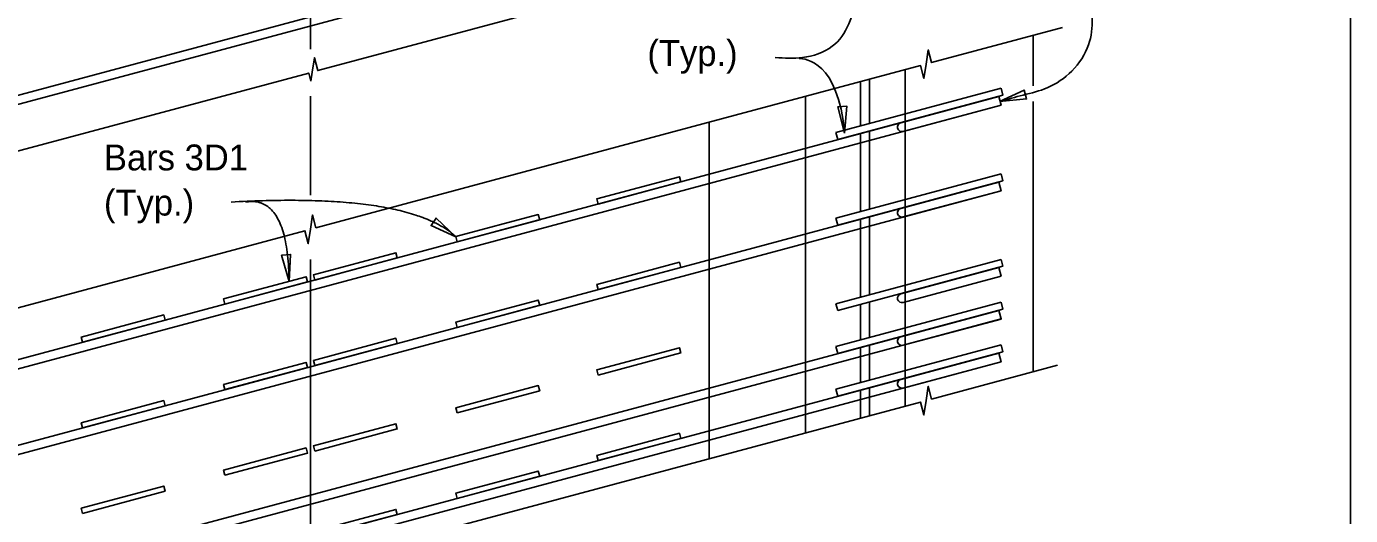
# Model space of a CAD drawing. Extents: x 120700.3 to 120754.4, y 120608.4 to 120631.3.
# Drawn here: x 120723.33 to 120731.07, y 120620 to 120622.85 of the extents above; entities that cross this region are included whole.
import ezdxf

# ---------------------------------------------------------------- set-up
doc = ezdxf.new("R2010")
doc.units = 0
for name, color, linetype in [('ActivePts-ConstElements', 7, 'Continuous'), ('BeamConc', 7, 'Continuous'), ('BeamConc_h', 7, 'Continuous'), ('CL_Major', 7, 'Continuous'), ('Dimension', 7, 'Continuous'), ('Rebar', 7, 'Continuous'), ('Rebar_h', 7, 'Continuous')]:
    doc.layers.add(name, color=color, linetype=linetype)

msp = doc.modelspace()

# ---------------------------------------------------------------- linework, layer by layer
at = {"layer": 'ActivePts-ConstElements'}
msp.add_lwpolyline([(120700.2847, 120610.4195), (120731.0726, 120610.4195), (120731.0726, 120629.8791), (120700.2847, 120629.8791)], close=True, dxfattribs=at)
at = {"layer": 'BeamConc'}
for p, q in [((120729.2163, 120622.802), (120729.2163, 120622.5065)), ((120727.8829, 120622.4448), (120727.8829, 120620.4782)), ((120729.2163, 120622.4153), (120729.2163, 120620.8354))]:
    msp.add_line(p, q, dxfattribs=at)
at = {"layer": 'BeamConc_h'}
for p, q in [((120728.4662, 120620.6344), (120728.4662, 120622.601)), ((120727.3204, 120622.2941), (120727.3204, 120620.3275))]:
    msp.add_line(p, q, dxfattribs=at)
at = {"layer": 'CL_Major'}
for p, q in [((120724.9871, 120622.7216), (120724.9871, 120627.6545)), ((120724.9871, 120621.8675), (120724.9871, 120622.4466)), ((120724.9871, 120619.9267), (120724.9871, 120621.4921))]:
    msp.add_line(p, q, dxfattribs=at)
at = {"layer": 'Dimension'}
for points in [[(120727.067, 120623.142), (120725.0301, 120622.5964), (120725.0101, 120622.6712), (120724.9976, 120622.5877), (120724.9897, 120622.5353)], [(120729.3877, 120622.8479), (120728.6218, 120622.6427), (120728.6018, 120622.7175), (120728.5893, 120622.634), (120728.5766, 120622.5503), (120728.5566, 120622.6252), (120727.0943, 120622.2335)], [(120724.9897, 120622.5353), (120724.9772, 120622.5821), (120722.272, 120621.8575)], [(120727.0943, 120622.2335), (120725.0196, 120621.6778), (120724.9996, 120621.7526), (120724.9871, 120621.6691), (120724.9744, 120621.5854), (120724.9544, 120621.6603), (120722.9331, 120621.1189)], [(120729.3589, 120620.8735), (120728.6218, 120620.6761), (120728.6018, 120620.7509), (120728.5893, 120620.6673), (120728.5766, 120620.5837), (120728.5566, 120620.6586), (120727.0943, 120620.2669)], [(120727.0943, 120620.2669), (120725.0196, 120619.7112), (120724.9996, 120619.786), (120724.9871, 120619.7024), (120724.9744, 120619.6188), (120724.9544, 120619.6937), (120722.9331, 120619.1523)]]:
    msp.add_lwpolyline(points, dxfattribs=at)
for points in [[(120729.0192, 120622.4159), (120729.1769, 120622.431), (120729.1631, 120622.4821)], [(120728.1126, 120622.2311), (120728.1251, 120622.389), (120728.0724, 120622.3843)], [(120725.8374, 120621.6255), (120725.7223, 120621.7343), (120725.6929, 120621.6903)], [(120724.8617, 120621.3641), (120724.8187, 120621.5165), (120724.8713, 120621.5222)]]:
    msp.add_lwpolyline(points, close=True, dxfattribs=at)
for points in [[(120728.1021, 120623.758), (120728.1838, 120623.0356), (120728.04, 120622.7381), (120727.8669, 120622.6727), (120727.7068, 120622.6727)], [(120729.7033, 120623.254), (120729.6282, 120623.254), (120729.54, 120623.1919), (120729.54, 120623.0645), (120729.54, 120622.7474), (120729.442, 120622.5938), (120729.2982, 120622.4957), (120729.1578, 120622.4533), (120729.0192, 120622.4159)]]:
    msp.add_spline(points, degree=3, dxfattribs=at)
for points, degree in [([(120727.8465, 120622.6672), (120727.8816, 120622.6656), (120728.0752, 120622.6508), (120728.1126, 120622.2311)], 3), ([(120724.5239, 120621.828), (120725.5579, 120621.8843), (120725.8374, 120621.6256)], 2), ([(120724.6078, 120621.828), (120724.856, 120621.8687), (120724.8618, 120621.3641)], 2)]:
    msp.add_open_spline(points, degree=degree, dxfattribs=at)
at = {"layer": 'Rebar'}
for p, q in [((120728.062, 120622.2338), (120729.028, 120622.4927)), ((120728.2058, 120622.5313), (120728.2058, 120622.2724)), ((120728.2579, 120622.5452), (120728.2579, 120622.2863)), ((120729.028, 120622.4927), (120729.0388, 120622.4524)), ((120729.0388, 120622.4524), (120728.0728, 120622.1936)), ((120728.4411, 120622.2909), (120729.0149, 120622.4446)), ((120729.0149, 120622.4446), (120729.0284, 120622.3943)), ((120729.0284, 120622.3943), (120728.4546, 120622.2406)), ((120728.0728, 120622.1936), (120728.062, 120622.2338)), ((120728.2058, 120622.2292), (120728.2058, 120621.7724)), ((120728.2579, 120622.2432), (120728.2579, 120621.7863)), ((120728.062, 120621.7338), (120729.028, 120621.9927)), ((120729.0388, 120621.9524), (120728.0728, 120621.6936)), ((120728.4411, 120621.7909), (120729.0149, 120621.9446)), ((120729.0149, 120621.9446), (120729.0284, 120621.8943)), ((120729.028, 120621.9927), (120729.0388, 120621.9524)), ((120729.0284, 120621.8943), (120728.4546, 120621.7406)), ((120728.0728, 120621.6936), (120728.062, 120621.7338)), ((120728.2058, 120621.7292), (120728.2058, 120621.2724)), ((120728.2579, 120621.7432), (120728.2579, 120621.2863)), ((120728.062, 120621.2338), (120729.028, 120621.4927)), ((120729.028, 120621.4927), (120729.0388, 120621.4524)), ((120729.0388, 120621.4524), (120728.0728, 120621.1936)), ((120728.4411, 120621.2909), (120729.0149, 120621.4446)), ((120729.0149, 120621.4446), (120729.0284, 120621.3943)), ((120729.0284, 120621.3943), (120728.4546, 120621.2406)), ((120728.062, 120620.9838), (120729.028, 120621.2427)), ((120728.0728, 120621.1936), (120728.062, 120621.2338)), ((120729.0388, 120621.2024), (120728.0728, 120620.9436)), ((120728.2058, 120621.2292), (120728.2058, 120621.0224)), ((120728.2579, 120621.2432), (120728.2579, 120621.0363)), ((120728.4411, 120621.0409), (120729.0149, 120621.1946)), ((120729.0149, 120621.1946), (120729.0284, 120621.1443)), ((120729.028, 120621.2427), (120729.0388, 120621.2024)), ((120729.0284, 120621.1443), (120728.4546, 120620.9906)), ((120728.062, 120620.7338), (120729.028, 120620.9927)), ((120728.0728, 120620.9436), (120728.062, 120620.9838)), ((120729.0388, 120620.9524), (120728.0728, 120620.6936)), ((120728.2058, 120620.9792), (120728.2058, 120620.7724)), ((120728.2579, 120620.9932), (120728.2579, 120620.7863)), ((120728.4411, 120620.7909), (120729.0149, 120620.9446)), ((120729.0149, 120620.9446), (120729.0284, 120620.8943)), ((120729.028, 120620.9927), (120729.0388, 120620.9524)), ((120729.0284, 120620.8943), (120728.4546, 120620.7406)), ((120728.0728, 120620.6936), (120728.062, 120620.7338)), ((120728.2058, 120620.7292), (120728.2058, 120620.5646)), ((120728.2579, 120620.7432), (120728.2579, 120620.5786))]:
    msp.add_line(p, q, dxfattribs=at)
for points in [[(120726.6708, 120621.8165), (120727.1537, 120621.9459), (120727.1457, 120621.9761), (120726.6627, 120621.8467)], [(120725.8455, 120621.5954), (120726.3285, 120621.7248), (120726.3204, 120621.755), (120725.8374, 120621.6256)], [(120725.0122, 120621.3721), (120725.4952, 120621.5015), (120725.4871, 120621.5317), (120725.0041, 120621.4023)], [(120726.6708, 120621.3165), (120727.1537, 120621.4459), (120727.1457, 120621.4761), (120726.6627, 120621.3467)], [(120724.4871, 120621.2314), (120724.97, 120621.3608), (120724.9619, 120621.391), (120724.479, 120621.2616)], [(120725.8455, 120621.0954), (120726.3285, 120621.2248), (120726.3204, 120621.255), (120725.8374, 120621.1256)], [(120723.6537, 120621.0081), (120724.1367, 120621.1375), (120724.1286, 120621.1677), (120723.6457, 120621.0383)], [(120725.0122, 120620.8721), (120725.4952, 120621.0015), (120725.4871, 120621.0317), (120725.0041, 120620.9023)], [(120726.6708, 120620.8165), (120727.1537, 120620.9459), (120727.1457, 120620.9761), (120726.6627, 120620.8467)], [(120724.4871, 120620.7314), (120724.97, 120620.8608), (120724.9619, 120620.891), (120724.479, 120620.7616)], [(120725.8455, 120620.5954), (120726.3285, 120620.7248), (120726.3204, 120620.755), (120725.8374, 120620.6256)], [(120723.6537, 120620.5081), (120724.1367, 120620.6375), (120724.1286, 120620.6677), (120723.6457, 120620.5383)], [(120725.0122, 120620.3721), (120725.4952, 120620.5015), (120725.4871, 120620.5317), (120725.0041, 120620.4023)], [(120726.6708, 120620.3165), (120727.1537, 120620.4459), (120727.1457, 120620.4761), (120726.6627, 120620.3467)], [(120724.4871, 120620.2314), (120724.97, 120620.3608), (120724.9619, 120620.391), (120724.479, 120620.2616)], [(120725.8455, 120620.0954), (120726.3285, 120620.2248), (120726.3204, 120620.255), (120725.8374, 120620.1256)], [(120723.6537, 120620.0081), (120724.1367, 120620.1375), (120724.1286, 120620.1677), (120723.6457, 120620.0383)], [(120725.0122, 120619.8721), (120725.4952, 120620.0015), (120725.4871, 120620.0317), (120725.0041, 120619.9023)]]:
    msp.add_lwpolyline(points, close=True, dxfattribs=at)
for centre in [(120728.4479, 120622.2657), (120728.4479, 120621.7657), (120728.4479, 120621.2657), (120728.4479, 120621.0157), (120728.4479, 120620.7657)]:
    msp.add_arc(centre, 0.026, 105, 285, dxfattribs=at)
at = {"layer": 'Rebar_h'}
msp.add_line((120729.0283, 120621.3944), (120729.0149, 120621.4446), dxfattribs=at)
for points in [[(120729.0253, 120623.9934), (120720.936, 120621.8259), (120720.9495, 120621.7757), (120729.0388, 120623.9431)], [(120729.0149, 120622.4446), (120720.936, 120620.2799), (120720.9494, 120620.2296), (120729.0283, 120622.3944)], [(120729.0149, 120621.9446), (120720.936, 120619.7799), (120720.9494, 120619.7296), (120729.0283, 120621.8944)], [(120729.0149, 120621.1946), (120720.936, 120619.0299), (120720.9494, 120618.9796), (120729.0283, 120621.1444)], [(120729.0149, 120620.9446), (120720.936, 120618.7799), (120720.9494, 120618.7296), (120729.0283, 120620.8944)]]:
    msp.add_lwpolyline(points, close=True, dxfattribs=at)

# ---------------------------------------------------------------- texts
at = {"layer": 'Dimension'}
for s, p in [('(Typ.)', (120726.9585, 120622.6233)), ('Bars 3D1 ', (120723.7788, 120622.013)), ('(Typ.)', (120723.7788, 120621.749))]:
    msp.add_text(s, height=0.1512, dxfattribs=at).set_placement(p)

doc.saveas('drawing.dxf')
